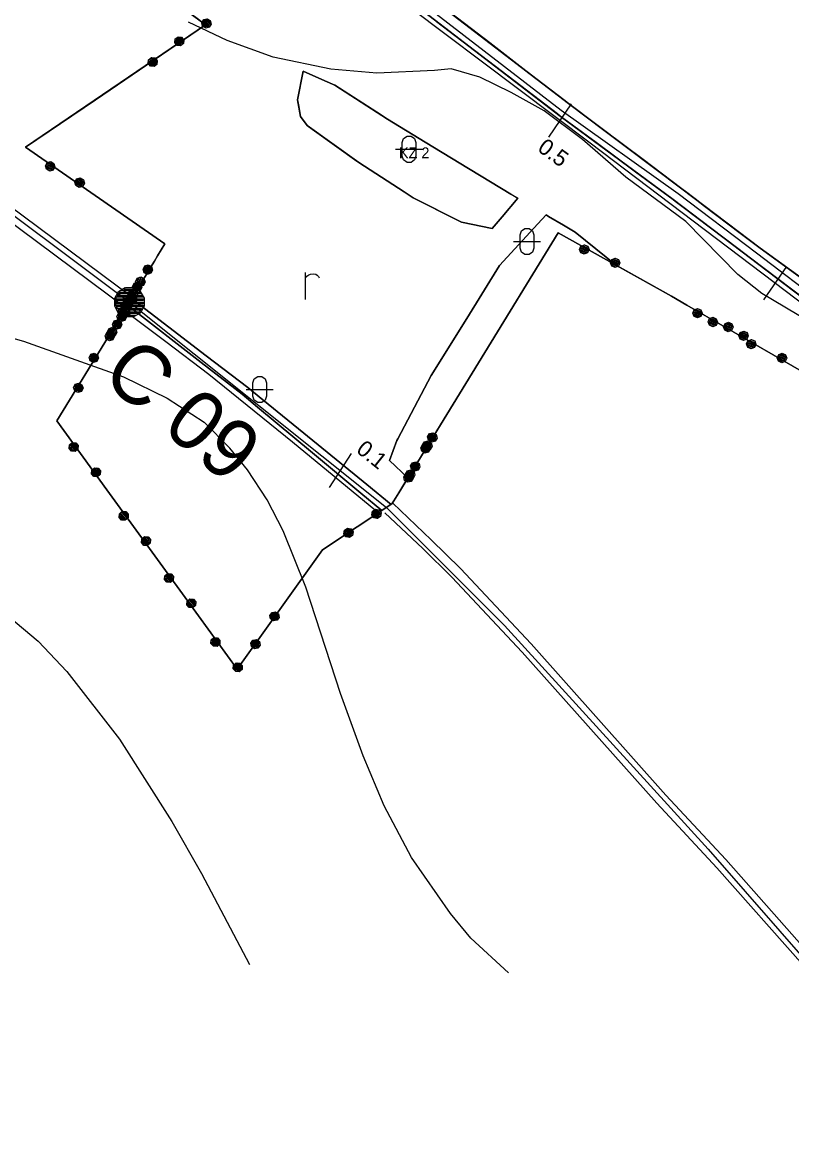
# Model space of a CAD drawing. Extents: x -645676 to -642474, y -1077513 to -1072613.
# Drawn here: x -645240.2 to -644954.9, y -1075496.8 to -1075082.2 of the extents above; entities that cross this region are included whole.
import ezdxf

# ---------------------------------------------------------------- set-up
doc = ezdxf.new("R2010")
doc.units = 0
for name, color, linetype in [('_cesty_Kunci', 7, 'Continuous'), ('_cesty_Slatinany', 7, 'Continuous'), ('KRAJ_ZELEN_STAV', 7, 'Continuous'), ('Krajinn__zele____popis___stav', 7, 'Continuous'), ('KULTURY_STAV', 7, 'Continuous'), ('KULTURY_ZNACKY', 7, 'Continuous'), ('OBVOD_PU', 7, 'Continuous'), ('Odvodnen__cesty_pr_kopem___navr_en_', 7, 'Continuous'), ('PC_MIMO_OBV', 7, 'Continuous'), ('PC_NAVRH', 7, 'Continuous'), ('PC_POPIS_NAVRH', 7, 'Continuous'), ('PC_STAN_NAVRH', 7, 'Continuous'), ('SPRAV_HR_STAV', 7, 'Continuous'), ('Vodn__plocha___st_vaj_c_', 7, 'Continuous'), ('Vodn__tok', 7, 'Continuous'), ('VRSTEVNICE', 7, 'Continuous')]:
    doc.layers.add(name, color=color, linetype=linetype)

# ---------------------------------------------------------------- blocks, each defined once
blk = doc.blocks.new('$944')
blk.add_line((0, 1.5), (0, -1.5))
blk = doc.blocks.new('$406')
blk.add_lwpolyline([(-0.19, 0.72), (0.2, 0.72), (0.54, 0.53), (0.73, 0.19), (0.73, -0.2), (0.54, -0.54), (0.2, -0.73), (-0.19, -0.73), (-0.53, -0.54), (-0.72, -0.2), (-0.72, 0.19), (-0.53, 0.53), (-0.2, 0.72), (-0.28, 0.64), (0.28, 0.64), (0.44, 0.56), (-0.44, 0.56), (-0.52, 0.48), (0.52, 0.48), (0.56, 0.4), (-0.55, 0.4), (-0.6, 0.32), (0.6, 0.32), (0.68, 0.24), (-0.59, 0.24), (-0.65, 0.24), (-0.68, 0.16), (0.59, 0.16), (0.68, 0.16), (0.68, 0.08), (-0.59, 0.08), (-0.68, 0.08), (-0.68, 0), (0.59, 0), (0.68, 0), (0.68, -0.08), (-0.59, -0.08), (-0.68, -0.08), (-0.68, -0.16), (0.59, -0.16), (0.68, -0.16), (0.65, -0.24), (-0.62, -0.24), (-0.65, -0.24), (-0.6, -0.32), (0.6, -0.32), (0.56, -0.4), (-0.55, -0.4), (-0.52, -0.48), (0.52, -0.48), (0.44, -0.56), (-0.44, -0.56), (-0.28, -0.64), (0.28, -0.64), (-0.02, -0.69)])
blk = doc.blocks.new('3$1600')
for points in [[(-0.5, 1.5), (-0.4, 1.79), (-0.15, 1.97), (0.16, 1.97), (0.41, 1.79), (0.51, 1.5), (0.51, 0.5), (0.41, 0.21), (0.16, 0.03), (-0.15, 0.03), (-0.4, 0.21), (-0.5, 0.5), (-0.5, 1.5)], [(-1, 1), (0.27, 1), (1, 1)]]:
    blk.add_lwpolyline(points)
blk = doc.blocks.new('$479')
for points in [[(0, 0), (0, 1.27), (0, 2)], [(0, 1.6), (0.1, 1.73), (0.23, 1.84), (0.37, 1.89), (0.6, 1.9), (0.77, 1.87), (0.87, 1.8), (0.96, 1.7), (1, 1.6)]]:
    blk.add_lwpolyline(points)
blk = doc.blocks.new('2$0620')
for points in [[(-1.07, 0.32), (-0.88, 0.13), (-0.88, -0.14), (-1.07, -0.33), (-1.34, -0.33), (-1.53, -0.14), (-1.53, 0.13), (-1.34, 0.32), (-1.07, 0.32), (-1.08, 0.28), (-1.32, 0.28), (-1.4, 0.2), (-1, 0.2), (-0.92, 0.12), (-1.48, 0.12), (-1.48, 0.04), (-0.92, 0.04), (-0.92, -0.04), (-1.48, -0.04), (-1.48, -0.12), (-0.92, -0.12), (-1, -0.2), (-1.4, -0.2), (-1.32, -0.28), (-1.08, -0.28)], [(1.43, 0.32), (1.62, 0.13), (1.62, -0.14), (1.43, -0.33), (1.16, -0.33), (0.97, -0.14), (0.97, 0.13), (1.16, 0.32), (1.43, 0.32), (1.4, 0.28), (1.16, 0.28), (1.08, 0.2), (1.48, 0.2), (1.56, 0.12), (1, 0.12), (1, 0.04), (1.56, 0.04), (1.56, -0.04), (1, -0.04), (1, -0.12), (1.56, -0.12), (1.48, -0.2), (1.08, -0.2), (1.16, -0.28), (1.4, -0.28)]]:
    blk.add_lwpolyline(points)

msp = doc.modelspace()

# ---------------------------------------------------------------- linework, layer by layer
at = {"layer": '_cesty_Kunci'}
for points in [[(-644891.19, -1075493.8), (-644917.56, -1075462.89), (-644932.09, -1075445.84), (-644947.3, -1075428.72), (-644979.37, -1075392.6), (-645001.52, -1075368.67), (-645051.49, -1075312.64), (-645077.68, -1075284.72), (-645088.58, -1075274.1), (-645102.77, -1075260.47)], [(-644894.59, -1075496.75), (-644920.98, -1075465.81), (-644950.66, -1075431.71), (-644982.71, -1075395.62), (-645004.85, -1075371.7), (-645054.81, -1075315.68), (-645080.9, -1075287.87), (-645091.72, -1075277.32), (-645105.75, -1075264.09)]]:
    msp.add_lwpolyline(points, dxfattribs=at)
at = {"layer": '_cesty_Slatinany'}
for points in [[(-645453.69, -1074993.83), (-645443.47, -1075002.14), (-645441.79, -1075003.56), (-645199.23, -1075184.27)], [(-645456.24, -1074996.92), (-645446.57, -1075005.41), (-645444.59, -1075007.09), (-645201.92, -1075187.88)]]:
    msp.add_lwpolyline(points, dxfattribs=at)
at = {"layer": 'KRAJ_ZELEN_STAV'}
msp.add_lwpolyline([(-645104.82, -1075118.07), (-645074.74, -1075136.42), (-645056.48, -1075147.41), (-645065.94, -1075158.65), (-645077.33, -1075156.31), (-645095.3, -1075147.24), (-645115.35, -1075134.23), (-645134.59, -1075120.47), (-645136.99, -1075117.11), (-645138.19, -1075110.91), (-645136, -1075100.38), (-645124.26, -1075105.53), (-645104.82, -1075118.07)], dxfattribs=at)
at = {"layer": 'KULTURY_STAV'}
for points in [[(-645083.47, -1075077.11), (-645066.84, -1075089.88), (-645052.34, -1075101.01), (-645038.9, -1075111.33), (-645037.68, -1075112.27), (-645024.5, -1075122.19), (-645009.99, -1075133.1), (-644995.58, -1075143.94), (-644994.27, -1075144.94), (-644990.68, -1075147.67), (-644987.2, -1075150.32), (-644973.98, -1075160.37), (-644966.6, -1075165.99), (-644946.66, -1075180.34)], [(-644946.66, -1075180.34), (-644966.6, -1075165.99), (-644973.98, -1075160.37), (-644987.2, -1075150.32), (-644990.68, -1075147.67), (-644994.27, -1075144.94), (-644995.58, -1075143.94), (-645009.99, -1075133.1), (-645024.5, -1075122.19), (-645037.68, -1075112.27), (-645038.9, -1075111.33), (-645052.34, -1075101.01), (-645066.84, -1075089.88), (-645083.47, -1075077.11)], [(-644951.22, -1075211.54), (-644979.55, -1075195.21), (-644993.8, -1075187), (-644999.48, -1075183.73), (-645019.88, -1075172.33), (-645035.16, -1075159.96), (-645039.45, -1075157.44), (-645045.01, -1075154.18), (-645045.97, -1075153.62), (-645049.03, -1075156.96), (-645063.2, -1075172.38), (-645075.36, -1075192), (-645088.52, -1075213.08), (-645100.97, -1075236.63), (-645101.26, -1075237.18), (-645104.07, -1075244.64), (-645097.26, -1075251.12), (-645100.6, -1075256.57), (-645102.46, -1075259.6), (-645103.12, -1075260.68), (-645103.46, -1075260.9), (-645112.46, -1075253.56), (-645130.5, -1075238.83), (-645150.98, -1075222.12), (-645156.57, -1075217.56), (-645171.94, -1075205.83), (-645199.7, -1075184.65), (-645201.21, -1075187.12), (-645173.82, -1075208.35), (-645158.7, -1075220.07), (-645152.96, -1075224.84), (-645132.56, -1075241.78), (-645114.59, -1075256.7), (-645106.83, -1075263.14), (-645128.85, -1075277.71), (-645160.51, -1075321.95), (-645174.84, -1075302.26), (-645192.07, -1075278.57), (-645208.85, -1075255.5), (-645227.42, -1075229.99), (-645207.27, -1075197.03), (-645195.57, -1075177.89), (-645194.64, -1075176.38), (-645192.89, -1075173.51), (-645191.2, -1075170.75), (-645190.01, -1075168.8), (-645187.27, -1075164.32), (-645238.93, -1075128.54), (-645213.04, -1075110.91), (-645172.22, -1075083.12), (-645176.31, -1075080.06)], [(-644947.6, -1075186.77), (-644970.16, -1075169.63), (-644974.89, -1075166.05), (-644995.18, -1075150.71), (-644998.16, -1075148.45), (-644998.85, -1075147.93), (-645012.81, -1075137.6), (-645027.42, -1075126.78), (-645040.7, -1075116.95), (-645041.72, -1075116.17), (-645055.27, -1075105.81), (-645069.93, -1075094.6), (-645086.59, -1075081.86)], [(-645086.59, -1075081.86), (-645069.93, -1075094.6), (-645055.27, -1075105.81), (-645041.72, -1075116.17), (-645040.7, -1075116.95), (-645027.42, -1075126.78), (-645012.81, -1075137.6), (-644998.85, -1075147.93), (-644998.16, -1075148.45), (-644995.18, -1075150.71), (-644974.89, -1075166.05), (-644970.16, -1075169.63), (-644947.6, -1075186.77)], [(-645136, -1075100.38), (-645128.02, -1075103.88), (-645124.26, -1075105.53), (-645108.72, -1075115.55), (-645104.82, -1075118.07), (-645090.85, -1075126.59), (-645074.74, -1075136.42), (-645074.17, -1075136.77), (-645059.05, -1075145.86), (-645056.48, -1075147.41), (-645062.25, -1075154.26), (-645065.94, -1075158.65), (-645077.34, -1075156.31), (-645079.1, -1075155.42), (-645095.3, -1075147.24), (-645098.6, -1075145.1), (-645115.35, -1075134.23), (-645116.1, -1075133.69), (-645132.7, -1075121.82), (-645134.59, -1075120.47), (-645136.99, -1075117.11), (-645137.82, -1075112.84), (-645138.19, -1075110.91), (-645136, -1075100.38)], [(-645138.19, -1075110.91), (-645137.82, -1075112.84), (-645136.99, -1075117.11), (-645134.59, -1075120.47), (-645132.7, -1075121.82), (-645116.1, -1075133.69), (-645115.35, -1075134.23), (-645098.6, -1075145.1), (-645095.3, -1075147.24), (-645079.1, -1075155.42), (-645077.34, -1075156.31), (-645065.94, -1075158.65), (-645062.25, -1075154.26), (-645056.48, -1075147.41), (-645059.05, -1075145.86), (-645074.17, -1075136.77), (-645074.74, -1075136.42), (-645090.85, -1075126.59), (-645104.82, -1075118.07), (-645108.72, -1075115.55), (-645124.26, -1075105.53), (-645128.02, -1075103.88), (-645136, -1075100.38), (-645138.19, -1075110.91)], [(-645045.97, -1075153.62), (-645045.01, -1075154.18), (-645039.45, -1075157.44), (-645035.16, -1075159.96), (-645019.88, -1075172.33), (-644999.48, -1075183.73), (-645041.54, -1075160.24), (-645100.6, -1075256.57), (-645097.26, -1075251.12), (-645104.07, -1075244.64), (-645101.26, -1075237.18), (-645100.97, -1075236.63), (-645088.52, -1075213.08), (-645075.36, -1075192), (-645063.2, -1075172.38), (-645049.03, -1075156.96), (-645045.97, -1075153.62)], [(-645199.7, -1075184.65), (-645171.94, -1075205.83), (-645156.57, -1075217.56), (-645150.98, -1075222.12), (-645130.5, -1075238.83), (-645112.46, -1075253.56), (-645103.46, -1075260.9), (-645103.12, -1075260.68), (-645106.83, -1075263.14), (-645114.59, -1075256.7), (-645132.56, -1075241.78), (-645152.96, -1075224.84), (-645158.7, -1075220.07), (-645173.82, -1075208.35), (-645201.21, -1075187.12), (-645199.7, -1075184.65)]]:
    msp.add_lwpolyline(points, dxfattribs=at)
at = {"layer": 'OBVOD_PU'}
msp.add_lwpolyline([(-644951.22, -1075211.54), (-644979.55, -1075195.21), (-644993.8, -1075187), (-644999.48, -1075183.73), (-645041.54, -1075160.24), (-645100.6, -1075256.57), (-645102.46, -1075259.6), (-645103.12, -1075260.68), (-645128.85, -1075277.71), (-645160.51, -1075321.95), (-645174.84, -1075302.26), (-645192.07, -1075278.57), (-645208.85, -1075255.5), (-645227.42, -1075229.99), (-645207.27, -1075197.03), (-645195.57, -1075177.89), (-645194.64, -1075176.38), (-645192.89, -1075173.51), (-645191.2, -1075170.75), (-645190.01, -1075168.8), (-645187.27, -1075164.32), (-645238.93, -1075128.54), (-645172.22, -1075083.12), (-645191.42, -1075068.75)], dxfattribs=at)
at = {"layer": 'Odvodnen__cesty_pr_kopem___navr_en_'}
msp.add_lwpolyline([(-645108.22, -1075264.01), (-645109.11, -1075263.25), (-645124.54, -1075250.53), (-645139.97, -1075237.81), (-645171.06, -1075212.79), (-645186.93, -1075200.7), (-645202.73, -1075188.76)], dxfattribs=at)
at = {"layer": 'PC_MIMO_OBV'}
for points in [[(-645431.84, -1075014.81), (-645330.83, -1075088.35), (-645200.48, -1075185.92)], [(-645105.18, -1075262.04), (-645061.38, -1075305.82), (-644985.84, -1075388.74), (-644891.59, -1075496.61)]]:
    msp.add_lwpolyline(points, dxfattribs=at)
at = {"layer": 'PC_NAVRH'}
msp.add_line((-645200.48, -1075185.92), (-645105.18, -1075262.04), dxfattribs=at)
msp.add_lwpolyline([(-644615.94, -1075324.38), (-644614.35, -1075298.06), (-644618.37, -1075293.21), (-644622.69, -1075291.24), (-644738.79, -1075265.15), (-644794.9, -1075254.19), (-644881.17, -1075235.85), (-644890.64, -1075231.29), (-644935.93, -1075197.93), (-645029.58, -1075127.01), (-645122.98, -1075056.71), (-645236.69, -1074970.28), (-645321.72, -1074906.75)], dxfattribs=at)
at = {"layer": 'SPRAV_HR_STAV'}
for p, q in [((-645191.42, -1075068.75), (-645172.22, -1075083.12)), ((-645172.22, -1075083.12), (-645238.93, -1075128.54)), ((-645238.93, -1075128.54), (-645187.27, -1075164.32)), ((-645100.6, -1075256.57), (-645041.54, -1075160.24)), ((-645041.54, -1075160.24), (-644999.48, -1075183.73)), ((-645187.27, -1075164.32), (-645190.01, -1075168.8)), ((-645191.2, -1075170.75), (-645192.89, -1075173.51)), ((-645190.01, -1075168.8), (-645191.2, -1075170.75)), ((-645192.89, -1075173.51), (-645194.64, -1075176.38)), ((-645195.57, -1075177.89), (-645207.27, -1075197.03)), ((-645194.64, -1075176.38), (-645195.57, -1075177.89)), ((-644999.48, -1075183.73), (-644993.8, -1075187)), ((-644993.8, -1075187), (-644979.55, -1075195.21)), ((-644979.55, -1075195.21), (-644951.22, -1075211.54)), ((-645207.27, -1075197.03), (-645227.42, -1075229.99)), ((-645227.42, -1075229.99), (-645208.85, -1075255.5)), ((-645208.85, -1075255.5), (-645192.07, -1075278.57)), ((-645102.46, -1075259.6), (-645100.6, -1075256.57)), ((-645128.85, -1075277.71), (-645103.12, -1075260.68)), ((-645103.12, -1075260.68), (-645102.46, -1075259.6)), ((-645192.07, -1075278.57), (-645174.84, -1075302.26)), ((-645160.51, -1075321.95), (-645128.85, -1075277.71)), ((-645174.84, -1075302.26), (-645160.51, -1075321.95))]:
    msp.add_line(p, q, dxfattribs=at)
at = {"layer": 'Vodn__plocha___st_vaj_c_'}
for points in [[(-645087.88, -1075073.72), (-645037.68, -1075112.27), (-644995.58, -1075143.94), (-644966.6, -1075165.99), (-644941.15, -1075184.31)], [(-644941.15, -1075184.31), (-644966.6, -1075165.99), (-644995.58, -1075143.94), (-645037.68, -1075112.27), (-645087.88, -1075073.72)], [(-644944.38, -1075189.22), (-644970.16, -1075169.63), (-644998.85, -1075147.93), (-645040.7, -1075116.95), (-645091.1, -1075078.42)], [(-645091.1, -1075078.42), (-645040.7, -1075116.95), (-644998.85, -1075147.93), (-644970.16, -1075169.63), (-644944.38, -1075189.22)]]:
    msp.add_lwpolyline(points, dxfattribs=at)
at = {"layer": 'Vodn__tok'}
msp.add_lwpolyline([(-644737.28, -1075262.07), (-644790.63, -1075250.71), (-644852.68, -1075237.9), (-644879.87, -1075231.93), (-644887.46, -1075228.4), (-644913.43, -1075209.05), (-644922.62, -1075202.32), (-644931.59, -1075195.91), (-644942.63, -1075187.1), (-644967.94, -1075167.74), (-644997, -1075145.82), (-645040.36, -1075114.96), (-645089.98, -1075076.71), (-645130.46, -1075044.8), (-645189.79, -1075000.02), (-645239.14, -1074962.61), (-645275.37, -1074935.26), (-645317.56, -1074903.59), (-645325.71, -1074895.16), (-645357.55, -1074846.07), (-645371.25, -1074825.24)], dxfattribs=at)
at = {"layer": 'VRSTEVNICE'}
for points in [[(-644948.35, -1075193.18), (-644965.95, -1075182.7), (-644974.92, -1075175.72), (-644994.15, -1075156.07), (-645016.42, -1075139.59), (-645032.46, -1075125.62), (-645046.7, -1075115), (-645058.86, -1075108.27), (-645070.5, -1075102.58), (-645081.11, -1075099.47), (-645087.29, -1075100.1), (-645108.66, -1075101.09), (-645125.75, -1075099.53), (-645147.11, -1075095.11), (-645164.2, -1075088.99), (-645178.59, -1075082.15)], [(-645402, -1075202.39), (-645400.62, -1075191.53), (-645397.63, -1075185.83), (-645391.79, -1075179.85), (-645386.66, -1075176.86), (-645377.26, -1075173.73), (-645369, -1075172.87), (-645359.01, -1075173.11), (-645346.79, -1075174.3), (-645328.56, -1075177.72), (-645284.12, -1075187.97), (-645239.69, -1075200.36), (-645202.68, -1075213.64), (-645186.51, -1075221.48), (-645172.74, -1075230.43)], [(-645059.91, -1075434.54), (-645073.81, -1075421.65), (-645081.35, -1075412.52), (-645095.83, -1075391.81), (-645105.97, -1075372.7), (-645113.79, -1075354.16), (-645122.19, -1075330.99), (-645135.07, -1075291.6), (-645143.47, -1075270.75), (-645149.41, -1075259.16), (-645156.65, -1075248.15), (-645163.17, -1075240.04), (-645172.74, -1075230.43)], [(-645318.56, -1075292.32), (-645312.19, -1075288.99), (-645305.24, -1075286.39), (-645296.55, -1075284.5), (-645289.89, -1075284.21), (-645273.09, -1075287.4), (-645259.19, -1075293.34), (-645245.14, -1075302.46), (-645234.28, -1075311.58), (-645223.7, -1075322.88), (-645204.15, -1075347.93), (-645184.75, -1075378.49), (-645173.74, -1075397.75), (-645155.93, -1075431.5)]]:
    msp.add_lwpolyline(points, dxfattribs=at)

# ---------------------------------------------------------------- block references
at = {"layer": 'KULTURY_ZNACKY', "xscale": 5, "yscale": 5}
for name, p in [('3$1600', (-645096.77, -1075134.27)), ('3$1600', (-645053.08, -1075168.44)), ('$479', (-645135.14, -1075184.97)), ('3$1600', (-645152.15, -1075223.32))]:
    msp.add_blockref(name, p, dxfattribs=at)
at = {"layer": 'PC_STAN_NAVRH'}
for p, xscale, yscale, rotation in [((-645040.75, -1075118.6), 4.999999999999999, 5, 145.529591), ((-644961.01, -1075178.94), 5, 4.999999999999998, 145.360526), ((-645122.35, -1075248.33), 4.999999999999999, 4.999999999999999, -33.00731400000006)]:
    msp.add_blockref('$944', p, dxfattribs=dict(at, xscale=xscale, yscale=yscale, rotation=rotation))
at = {"layer": 'PC_STAN_NAVRH', "xscale": 7.5, "yscale": 7.5}
msp.add_blockref('$406', (-645200.48, -1075185.92), dxfattribs=at)
at = {"layer": 'SPRAV_HR_STAV'}
for p, xscale, yscale, rotation in [((-645177.41, -1075079.24), 5, 4.999999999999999, -31.171866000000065), ((-645186.69, -1075092.97), 5.000000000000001, 4.999999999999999, -142.01136600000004), ((-645224.54, -1075138.5), 5, 5, -29.02925500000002), ((-645026.26, -1075168.77), 5.000000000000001, 5, -23.408971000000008), ((-645196.4, -1075179.25), 5.000000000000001, 4.999999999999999, -117.28678300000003), ((-645200.34, -1075185.67), 5, 4.999999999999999, -117.31697100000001), ((-645199.13, -1075183.74), 5.000000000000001, 5, -117.22943600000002), ((-645202, -1075188.45), 5, 5.000000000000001, -117.20817100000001), ((-645204.7, -1075192.82), 5, 5.000000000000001, -117.273106), ((-645203.82, -1075191.28), 5, 5, -117.46830100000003), ((-644984.31, -1075192.46), 5, 4.999999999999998, -24.168401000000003), ((-644978.64, -1075195.74), 4.999999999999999, 5, -24.187498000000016), ((-644964.39, -1075203.95), 4.999999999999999, 5, -24.199757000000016), ((-645216.4, -1075211.96), 5, 5.000000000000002, -117.27574700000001), ((-645093.3, -1075244.69), 5, 5, 59.476093), ((-645091.45, -1075241.65), 5, 5.000000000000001, 59.508304), ((-645217.12, -1075244.14), 5, 5, -48.60562800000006), ((-645093.99, -1075245.75), 4.999999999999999, 5.000000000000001, 59.592682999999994), ((-645114.26, -1075268.05), 4.999999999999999, 5, 34.08419), ((-645198.56, -1075269.65), 5.000000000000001, 4.999999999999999, -48.628448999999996), ((-645181.78, -1075292.72), 5, 5, -48.62997800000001), ((-645150.33, -1075307.72), 5, 5, 55.360551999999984), ((-645164.54, -1075316.41), 5, 5, -48.61207700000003)]:
    msp.add_blockref('2$0620', p, dxfattribs=dict(at, xscale=xscale, yscale=yscale, rotation=rotation))

# ---------------------------------------------------------------- texts
at = {"layer": 'Krajinn__zele____popis___stav'}
msp.add_text('KZ 2', height=4, dxfattribs=at).set_placement((-645100.51, -1075132.59))
at = {"layer": 'PC_POPIS_NAVRH'}
msp.add_text('C 09', height=22, rotation=320.398, dxfattribs=at).set_placement((-645211.63, -1075214.33))
at = {"layer": 'PC_STAN_NAVRH'}
for s, rotation, p in [('0.5', 324.008, (-645049.51, -1075129.65)), ('0.1', 321.372, (-645116.73, -1075241.3))]:
    msp.add_text(s, height=6, rotation=rotation, dxfattribs=at).set_placement(p)

doc.saveas('drawing.dxf')
